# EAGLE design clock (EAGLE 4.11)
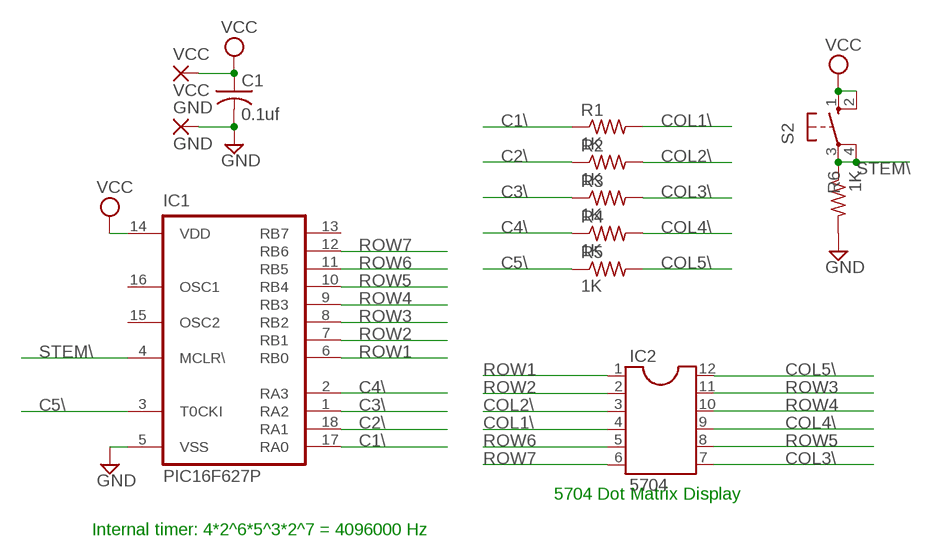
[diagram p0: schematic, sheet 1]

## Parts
C1  0.1uf  C-US025-025X050  [C025-025X050]
GND  GND  1,6/0,8  [1,6/0,8]
IC1  PIC16F627P  PIC16C622P  [DIL18]
IC2  5704  DIL12  [DIL12]
R1  1K  R-US_0207/10  [0207/10]
R2  1K  R-US_0207/10  [0207/10]
R3  1K  R-US_0207/10  [0207/10]
R4  1K  R-US_0207/10  [0207/10]
R5  1K  R-US_0207/10  [0207/10]
R6  1K  R-US_0207/10  [0207/10]
S2  10-XX  [B3F-10XX]
VCC  VCC  1,6/0,8  [1,6/0,8]

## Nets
C1\: IC1.17(RA0) R1.1
C2\: IC1.18(RA1) R2.1
C3\: IC1.1(RA2) R3.1
C4\: IC1.2(RA3) R4.1
C5\: IC1.3(T0CKI) R5.1
COL1\: IC2.4 R1.2
COL2\: IC2.3 R2.2
COL3\: IC2.7 R3.2
COL4\: IC2.9 R4.2
COL5\: IC2.12 R5.2
GND [Supply]: C1.2 GND.1(P) IC1.5(VSS) R6.2
ROW1: IC1.6(RB0) IC2.1
ROW2: IC1.7(RB1) IC2.2
ROW3: IC1.8(RB2) IC2.11
ROW4: IC1.9(RB3) IC2.10
ROW5: IC1.10(RB4) IC2.8
ROW6: IC1.11(RB5) IC2.5
ROW7: IC1.12(RB6) IC2.6
STEM\: IC1.4(MCLR\) R6.1 S2.3(P) S2.4(P1)
VCC [Supply]: C1.1 IC1.14(VDD) S2.1(S) S2.2(S1) VCC.1(P)
Unconnected: IC1.13(RB7) IC1.15(OSC2) IC1.16(OSC1)

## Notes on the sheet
- 5704 Dot Matrix Display
- Internal timer: 4*2^6*5^3*2^7 = 4096000 Hz

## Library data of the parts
C1 = rcl:C-US: CAPACITOR, American symbol
GND VCC = wirepad:1,6/0,8: THROUGH-HOLE PAD
IC1 = microchip:PIC16C*: MICROCONTROLLER PIC16C5X family: EPROM/ROM-based PIC16C55X family: EPROM-based PIC16C6X family PIC16CE62X family: analog comparators/EEPROM data memory PIC16C7X family: A/D converter PIC16C71X family: A/D converter PIC16F8X family: flash EEPROM Pin compatible devices: PIC16C154, PIC16CR154,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
IC2 = ic-package:DIL12: Dual In Line
R1-R6 = rcl:R-US_: RESISTOR, American symbol
S2 = switch-omron:10-XX: OMRON SWITCH

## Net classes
1 Supply: width 0.406 mm

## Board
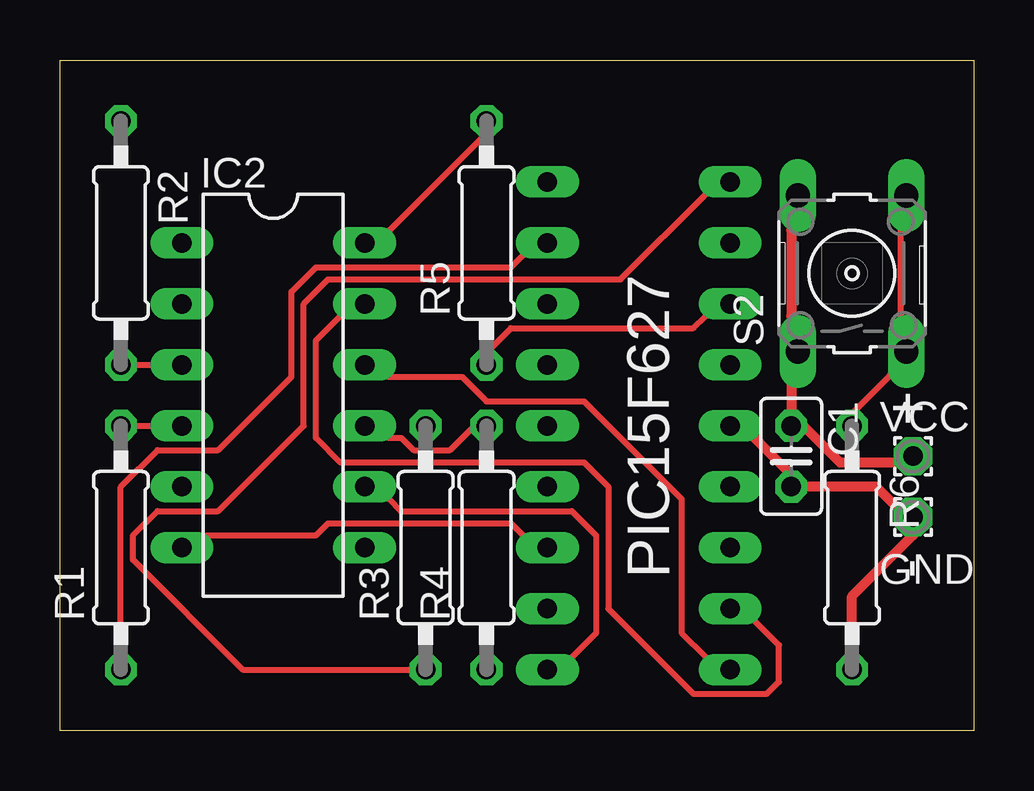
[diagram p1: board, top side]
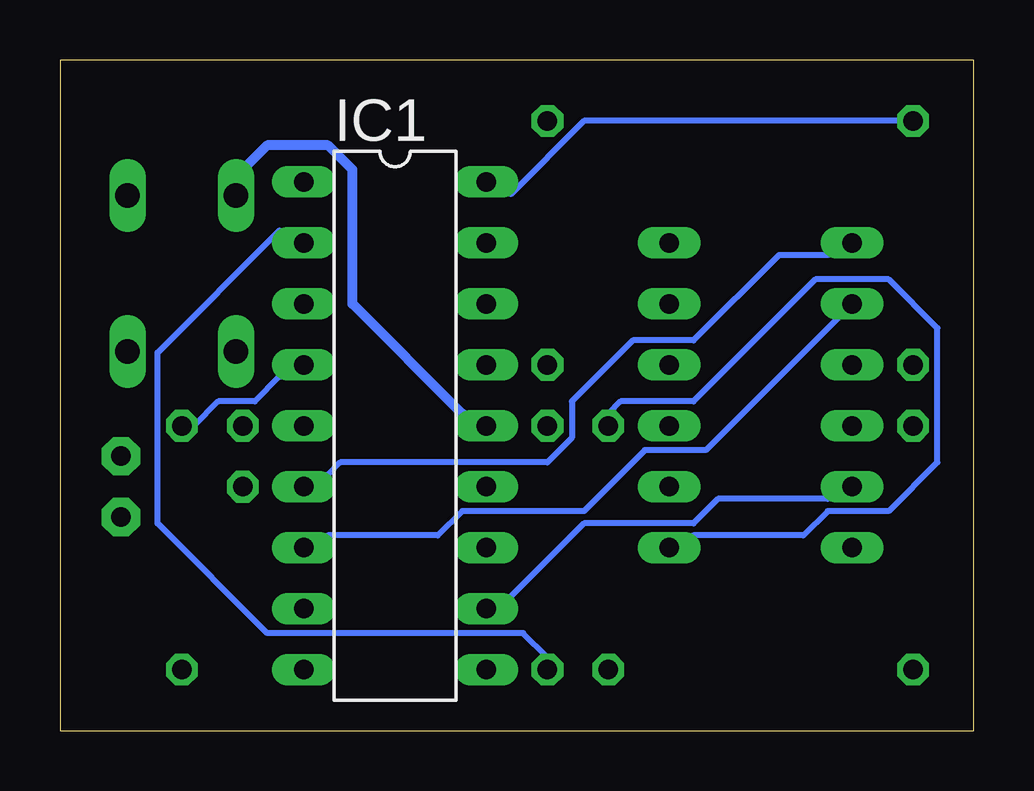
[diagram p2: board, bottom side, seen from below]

Size 38.1 x 27.94 mm. Coordinates in mm from the lower left corner, seen from the top.
Outline: 0,0 0,12.7 0,27.94 38.1,27.94 38.1,0 0,0
Copper layers (1*16): Top 0.035mm / dielectric 1.5mm / Bottom 0.035mm
Design rules "default": minimum track width 10mil, minimum drill 24mil, track to track 8mil, track to pad 8mil, pad to pad 8mil, via to via 8mil, smd to smd 8mil, copper to edge 40mil, drill to drill 8mil, minimum pad ring 10mil, minimum via ring 8mil, stop-mask expansion 4mil, vias tented up to drill 0mil, thermal gap 10mil

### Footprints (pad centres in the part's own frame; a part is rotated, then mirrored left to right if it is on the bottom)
C025-025X050 = drill 0.813 octagon: 1 -1.27,0; 2 1.27,0
1,6/0,8 = drill 0.813 pad 1.6 octagon: 1 0,0
DIL18 = drill 0.813 long: 1 -10.16,-3.81; 2 -7.62,-3.81; 3 -5.08,-3.81; 4 -2.54,-3.81; 5 0,-3.81; 6 2.54,-3.81; 7 5.08,-3.81; 8 7.62,-3.81; 9 10.16,-3.81; 10 10.16,3.81; 11 7.62,3.81; 12 5.08,3.81; 13 2.54,3.81; 14 0,3.81; 15 -2.54,3.81; 16 -5.08,3.81; 17 -7.62,3.81; 18 -10.16,3.81
DIL12 = drill 0.813 long: 1 -6.35,-3.81; 2 -3.81,-3.81; 3 -1.27,-3.81; 4 1.27,-3.81; 5 3.81,-3.81; 6 6.35,-3.81; 7 6.35,3.81; 8 3.81,3.81; 9 1.27,3.81; 10 -1.27,3.81; 11 -3.81,3.81; 12 -6.35,3.81
0207/10 = drill 0.813 octagon: 1 -5.08,0; 2 5.08,0
B3F-10XX = drill 1.016 long: 1 -3.251,2.261; 2 3.251,2.261; 3 -3.251,-2.261; 4 3.251,-2.261

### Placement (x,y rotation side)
C1  30.48,11.43 270 top
GND  35.56,8.89 0 top
IC1  24.13,12.7 270 bottom
IC2  8.89,13.97 270 top
R1  2.54,7.62 90 top
R2  2.54,20.32 270 top
R3  15.24,7.62 90 top
R4  17.78,7.62 90 top
R5  17.78,20.32 90 top
R6  33.02,7.62 270 top
S2  33.02,19.05 90 top
VCC  35.56,11.43 0 top

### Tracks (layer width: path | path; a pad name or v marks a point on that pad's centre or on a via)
C1\
  Top 0.254: R1.1 2.54,3.05 2.54,10.16 4.06,11.68 6.6,11.68 9.65,14.73 9.65,18.29 10.67,19.3 18.8,19.3 19.3,19.81 IC1.17
C2\
  Bottom 0.254: R2.1 3.05,25.4 16.26,25.4 19.3,22.35 IC1.18
C3\
  Top 0.254: R3.1 14.73,2.54 7.62,2.54 3.05,7.11 3.05,8.13 4.06,9.14 6.6,9.14 10.16,12.7 10.16,17.78 11.18,18.8 23.37,18.8 26.92,22.35 IC1.1
C4\
  Bottom 0.254: R4.1 17.78,3.05 18.8,4.06 29.46,4.06 34.04,8.64 34.04,15.75 28.96,20.83 IC1.2
C5\
  Top 0.254: R5.1 17.78,15.75 18.8,16.76 26.42,16.76 26.92,17.27 IC1.3
COL1\
  Top 0.254: R1.2 3.05,12.7 4.06,12.7 IC2.4
COL2\
  Top 0.254: R2.2 3.05,15.24 4.06,15.24 IC2.3
COL3\
  Bottom 0.254: IC2.7 11.68,8.13 7.11,8.13 6.1,9.14 3.56,9.14 1.52,11.18 1.52,16.76 3.56,18.8 6.6,18.8 11.68,13.72 14.73,13.72 15.24,13.21 R3.2
COL4\
  Top 0.254: IC2.9 13.72,12.19 14.22,12.19 14.73,11.68 16.26,11.68 17.27,12.7 R4.2
COL5\
  Top 0.254: IC2.12 13.72,20.83 17.78,24.89 R5.2
GND
  Top 0.406: IC1.5 28.96,12.19 30.48,10.67 C1.2 30.99,10.16 34.04,10.16 35.05,9.14 GND.1 35.56,8.13 33.02,5.59 33.02,3.05 R6.2
ROW1
  Bottom 0.254: IC2.1 6.1,19.81 8.13,19.81 11.68,16.26 14.22,16.26 16.76,13.72 16.76,12.19 17.78,11.18 26.42,11.18 26.92,10.67 IC1.6
ROW2
  Bottom 0.254: IC1.7 26.92,8.13 22.35,8.13 21.34,9.14 16.26,9.14 13.72,11.68 11.18,11.68 5.59,17.27 IC2.2
ROW3
  Top 0.254: IC1.8 28.96,4.57 29.97,3.56 29.97,2.03 29.46,1.52 26.42,1.52 22.86,5.08 22.86,10.16 21.84,11.18 11.68,11.18 10.67,12.19 10.67,16.26 11.68,17.27 IC2.11
ROW4
  Top 0.254: IC2.10 13.72,14.73 16.76,14.73 17.78,13.72 21.84,13.72 25.91,9.65 25.91,4.06 26.92,3.05 IC1.9
ROW5
  Top 0.254: IC1.10 21.34,3.05 22.35,4.06 22.35,8.13 21.34,9.14 14.22,9.14 13.72,9.65 IC2.8
ROW6
  Bottom 0.254: IC2.5 6.1,9.65 10.67,9.65 11.68,8.64 16.26,8.64 19.3,5.59 IC1.11
ROW7
  Top 0.254: IC2.6 6.1,8.13 10.67,8.13 11.18,8.64 18.8,8.64 19.3,8.13 IC1.12
STEM\
  Top 0.254: R6.1 33.02,13.21 34.54,14.73 S2.3 35.05,17.27 35.05,20.83 S2.4
  Bottom 0.254: IC1.4 28.96,14.73 29.97,13.72 31.5,13.72 32.51,12.7 R6.1
VCC
  Top 0.406: VCC.1 35.05,11.18 32.51,11.18 30.99,12.7 C1.1 30.48,13.21 30.48,14.73 S2.1 30.48,17.27 30.48,20.83 S2.2
  Bottom 0.406: IC1.14 21.34,13.21 25.91,17.78 25.91,23.37 26.92,24.38 29.46,24.38 30.48,23.37 S2.2

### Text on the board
tPlace: + | PIC15F627 | -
